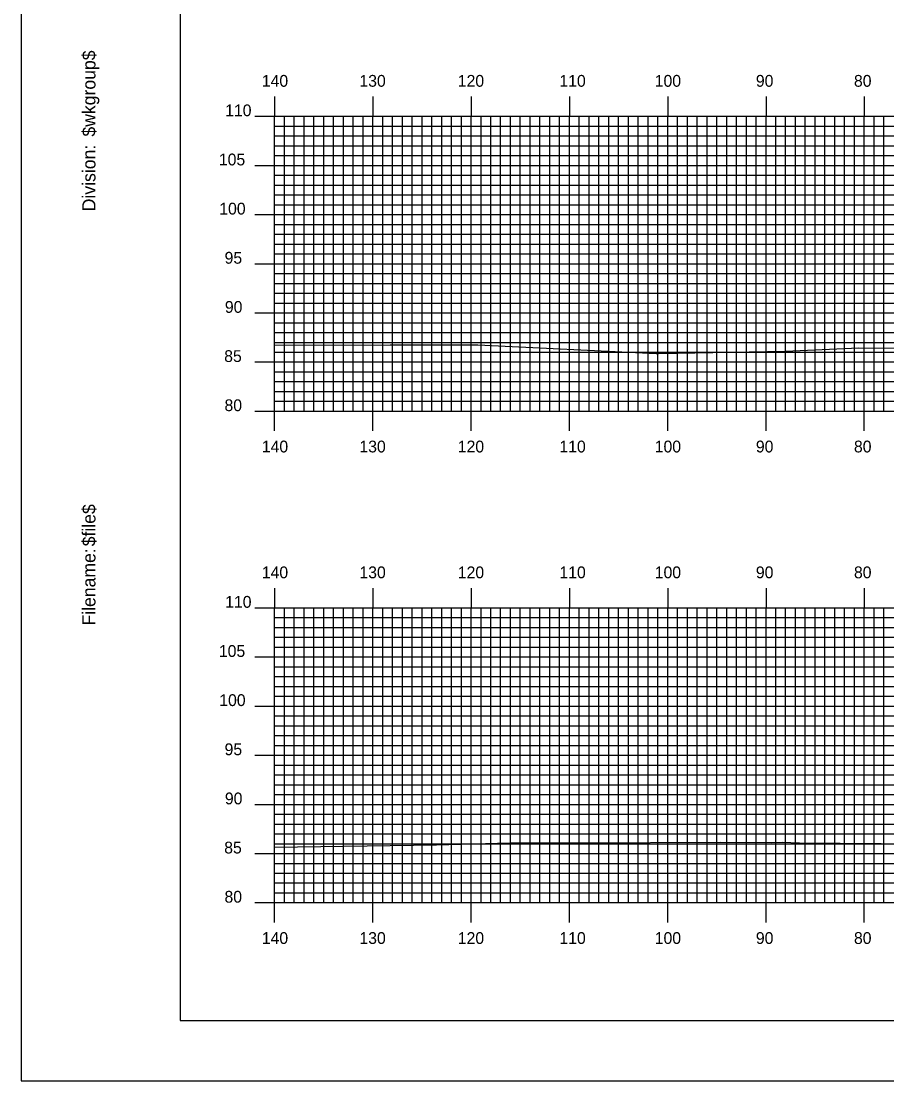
# Model space of a CAD drawing. Extents: x 1762578 to 1762921, y 442591 to 442811.
# Drawn here: x 1762578 to 1762666.1, y 442590.5 to 442698.3 of the extents above; entities that cross this region are included whole.
import ezdxf

# ---------------------------------------------------------------- set-up
doc = ezdxf.new("R2010")
doc.units = 0
for name, color, linetype in [('BORDER', 7, 'Continuous'), ('H_V ANNOTATION', 7, 'Continuous'), ('MAJOR', 7, 'Continuous'), ('MINOR', 7, 'Continuous'), ('PLOT BOUNDARY', 7, 'Continuous'), ('S_Roadway_Centerline', 7, 'Continuous')]:
    doc.layers.add(name, color=color, linetype=linetype)

msp = doc.modelspace()

# ---------------------------------------------------------------- linework, layer by layer
at = {"layer": 'BORDER'}
msp.add_lwpolyline([(1762594.18, 442596.67), (1762914.18, 442596.67), (1762914.18, 442806.67), (1762594.18, 442806.67)], close=True, dxfattribs=at)
at = {"layer": 'MAJOR'}
for p, q in [((1762603.78, 442690.67), (1762603.78, 442688.67)), ((1762613.78, 442690.67), (1762613.78, 442688.67)), ((1762623.78, 442690.67), (1762623.78, 442688.67)), ((1762633.78, 442690.67), (1762633.78, 442688.67)), ((1762643.78, 442690.67), (1762643.78, 442688.67)), ((1762653.78, 442690.67), (1762653.78, 442688.67)), ((1762663.78, 442690.67), (1762663.78, 442688.67)), ((1762601.78, 442688.67), (1762603.78, 442688.67)), ((1762603.78, 442688.67), (1762883.78, 442688.67)), ((1762603.78, 442658.67), (1762603.78, 442688.67)), ((1762603.78, 442658.67), (1762603.78, 442688.67)), ((1762603.78, 442688.67), (1762883.78, 442688.67)), ((1762613.78, 442658.67), (1762613.78, 442688.67)), ((1762623.78, 442658.67), (1762623.78, 442688.67)), ((1762633.78, 442658.67), (1762633.78, 442688.67)), ((1762643.78, 442658.67), (1762643.78, 442688.67)), ((1762653.78, 442658.67), (1762653.78, 442688.67)), ((1762663.78, 442658.67), (1762663.78, 442688.67)), ((1762601.78, 442683.67), (1762603.78, 442683.67)), ((1762603.78, 442683.67), (1762883.78, 442683.67)), ((1762601.78, 442678.67), (1762603.78, 442678.67)), ((1762603.78, 442678.67), (1762883.78, 442678.67)), ((1762601.78, 442673.67), (1762603.78, 442673.67)), ((1762603.78, 442673.67), (1762883.78, 442673.67)), ((1762601.78, 442668.67), (1762603.78, 442668.67)), ((1762603.78, 442668.67), (1762883.78, 442668.67)), ((1762601.78, 442663.67), (1762603.78, 442663.67)), ((1762603.78, 442663.67), (1762883.78, 442663.67)), ((1762601.78, 442658.67), (1762603.78, 442658.67)), ((1762603.78, 442658.67), (1762883.78, 442658.67)), ((1762603.78, 442658.67), (1762883.78, 442658.67)), ((1762603.78, 442656.66), (1762603.78, 442658.67)), ((1762613.78, 442656.66), (1762613.78, 442658.67)), ((1762623.78, 442656.66), (1762623.78, 442658.67)), ((1762633.78, 442656.66), (1762633.78, 442658.67)), ((1762643.78, 442656.66), (1762643.78, 442658.67)), ((1762653.78, 442656.66), (1762653.78, 442658.67)), ((1762663.78, 442656.66), (1762663.78, 442658.67)), ((1762603.78, 442640.67), (1762603.78, 442638.67)), ((1762613.78, 442640.67), (1762613.78, 442638.67)), ((1762623.78, 442640.67), (1762623.78, 442638.67)), ((1762633.78, 442640.67), (1762633.78, 442638.67)), ((1762643.78, 442640.67), (1762643.78, 442638.67)), ((1762653.78, 442640.67), (1762653.78, 442638.67)), ((1762663.78, 442640.67), (1762663.78, 442638.67)), ((1762601.78, 442638.67), (1762603.78, 442638.67)), ((1762603.78, 442638.67), (1762883.78, 442638.67)), ((1762603.78, 442608.67), (1762603.78, 442638.67)), ((1762603.78, 442608.67), (1762603.78, 442638.67)), ((1762603.78, 442638.67), (1762883.78, 442638.67)), ((1762613.78, 442608.67), (1762613.78, 442638.67)), ((1762623.78, 442608.67), (1762623.78, 442638.67)), ((1762633.78, 442608.67), (1762633.78, 442638.67)), ((1762643.78, 442608.67), (1762643.78, 442638.67)), ((1762653.78, 442608.67), (1762653.78, 442638.67)), ((1762663.78, 442608.67), (1762663.78, 442638.67)), ((1762601.78, 442633.67), (1762603.78, 442633.67)), ((1762603.78, 442633.67), (1762883.78, 442633.67)), ((1762601.78, 442628.67), (1762603.78, 442628.67)), ((1762603.78, 442628.67), (1762883.78, 442628.67)), ((1762601.78, 442623.67), (1762603.78, 442623.67)), ((1762603.78, 442623.67), (1762883.78, 442623.67)), ((1762601.78, 442618.67), (1762603.78, 442618.67)), ((1762603.78, 442618.67), (1762883.78, 442618.67)), ((1762601.78, 442613.67), (1762603.78, 442613.67)), ((1762603.78, 442613.67), (1762883.78, 442613.67)), ((1762601.78, 442608.67), (1762603.78, 442608.67)), ((1762603.78, 442608.67), (1762883.78, 442608.67)), ((1762603.78, 442608.67), (1762883.78, 442608.67)), ((1762603.78, 442606.66), (1762603.78, 442608.67)), ((1762613.78, 442606.66), (1762613.78, 442608.67)), ((1762623.78, 442606.66), (1762623.78, 442608.67)), ((1762633.78, 442606.66), (1762633.78, 442608.67)), ((1762643.78, 442606.66), (1762643.78, 442608.67)), ((1762653.78, 442606.66), (1762653.78, 442608.67)), ((1762663.78, 442606.66), (1762663.78, 442608.67))]:
    msp.add_line(p, q, dxfattribs=at)
at = {"layer": 'MINOR'}
for p, q in [((1762604.78, 442658.67), (1762604.78, 442688.67)), ((1762605.78, 442658.67), (1762605.78, 442688.67)), ((1762606.78, 442658.67), (1762606.78, 442688.67)), ((1762607.78, 442658.67), (1762607.78, 442688.67)), ((1762608.78, 442658.67), (1762608.78, 442688.67)), ((1762609.78, 442658.67), (1762609.78, 442688.67)), ((1762610.78, 442658.67), (1762610.78, 442688.67)), ((1762611.78, 442658.67), (1762611.78, 442688.67)), ((1762612.78, 442658.67), (1762612.78, 442688.67)), ((1762614.78, 442658.67), (1762614.78, 442688.67)), ((1762615.78, 442658.67), (1762615.78, 442688.67)), ((1762616.78, 442658.67), (1762616.78, 442688.67)), ((1762617.78, 442658.67), (1762617.78, 442688.67)), ((1762618.78, 442658.67), (1762618.78, 442688.67)), ((1762619.78, 442658.67), (1762619.78, 442688.67)), ((1762620.78, 442658.67), (1762620.78, 442688.67)), ((1762621.78, 442658.67), (1762621.78, 442688.67)), ((1762622.78, 442658.67), (1762622.78, 442688.67)), ((1762624.78, 442658.67), (1762624.78, 442688.67)), ((1762625.78, 442658.67), (1762625.78, 442688.67)), ((1762626.78, 442658.67), (1762626.78, 442688.67)), ((1762627.78, 442658.67), (1762627.78, 442688.67)), ((1762628.78, 442658.67), (1762628.78, 442688.67)), ((1762629.78, 442658.67), (1762629.78, 442688.67)), ((1762630.78, 442658.67), (1762630.78, 442688.67)), ((1762631.78, 442658.67), (1762631.78, 442688.67)), ((1762632.78, 442658.67), (1762632.78, 442688.67)), ((1762634.78, 442658.67), (1762634.78, 442688.67)), ((1762635.78, 442658.67), (1762635.78, 442688.67)), ((1762636.78, 442658.67), (1762636.78, 442688.67)), ((1762637.78, 442658.67), (1762637.78, 442688.67)), ((1762638.78, 442658.67), (1762638.78, 442688.67)), ((1762639.78, 442658.67), (1762639.78, 442688.67)), ((1762640.78, 442658.67), (1762640.78, 442688.67)), ((1762641.78, 442658.67), (1762641.78, 442688.67)), ((1762642.78, 442658.67), (1762642.78, 442688.67)), ((1762644.78, 442658.67), (1762644.78, 442688.67)), ((1762645.78, 442658.67), (1762645.78, 442688.67)), ((1762646.78, 442658.67), (1762646.78, 442688.67)), ((1762647.78, 442658.67), (1762647.78, 442688.67)), ((1762648.78, 442658.67), (1762648.78, 442688.67)), ((1762649.78, 442658.67), (1762649.78, 442688.67)), ((1762650.78, 442658.67), (1762650.78, 442688.67)), ((1762651.78, 442658.67), (1762651.78, 442688.67)), ((1762652.78, 442658.67), (1762652.78, 442688.67)), ((1762654.78, 442658.67), (1762654.78, 442688.67)), ((1762655.78, 442658.67), (1762655.78, 442688.67)), ((1762656.78, 442658.67), (1762656.78, 442688.67)), ((1762657.78, 442658.67), (1762657.78, 442688.67)), ((1762658.78, 442658.67), (1762658.78, 442688.67)), ((1762659.78, 442658.67), (1762659.78, 442688.67)), ((1762660.78, 442658.67), (1762660.78, 442688.67)), ((1762661.78, 442658.67), (1762661.78, 442688.67)), ((1762662.78, 442658.67), (1762662.78, 442688.67)), ((1762664.78, 442658.67), (1762664.78, 442688.67)), ((1762665.78, 442658.67), (1762665.78, 442688.67)), ((1762603.78, 442687.67), (1762883.78, 442687.67)), ((1762603.78, 442687.67), (1762605.78, 442687.67)), ((1762603.78, 442686.67), (1762883.78, 442686.67)), ((1762603.78, 442686.67), (1762605.78, 442686.67)), ((1762603.78, 442685.67), (1762883.78, 442685.67)), ((1762603.78, 442685.67), (1762605.78, 442685.67)), ((1762603.78, 442684.67), (1762883.78, 442684.67)), ((1762603.78, 442684.67), (1762605.78, 442684.67)), ((1762603.78, 442682.67), (1762883.78, 442682.67)), ((1762603.78, 442682.67), (1762605.78, 442682.67)), ((1762603.78, 442681.67), (1762883.78, 442681.67)), ((1762603.78, 442681.67), (1762605.78, 442681.67)), ((1762603.78, 442680.67), (1762883.78, 442680.67)), ((1762603.78, 442680.67), (1762605.78, 442680.67)), ((1762603.78, 442679.67), (1762883.78, 442679.67)), ((1762603.78, 442679.67), (1762605.78, 442679.67)), ((1762603.78, 442677.67), (1762883.78, 442677.67)), ((1762603.78, 442677.67), (1762605.78, 442677.67)), ((1762603.78, 442676.67), (1762883.78, 442676.67)), ((1762603.78, 442676.67), (1762605.78, 442676.67)), ((1762603.78, 442675.67), (1762883.78, 442675.67)), ((1762603.78, 442675.67), (1762605.78, 442675.67)), ((1762603.78, 442674.67), (1762883.78, 442674.67)), ((1762603.78, 442674.67), (1762605.78, 442674.67)), ((1762603.78, 442672.67), (1762883.78, 442672.67)), ((1762603.78, 442672.67), (1762605.78, 442672.67)), ((1762603.78, 442671.67), (1762883.78, 442671.67)), ((1762603.78, 442671.67), (1762605.78, 442671.67)), ((1762603.78, 442670.67), (1762883.78, 442670.67)), ((1762603.78, 442670.67), (1762605.78, 442670.67)), ((1762603.78, 442669.67), (1762883.78, 442669.67)), ((1762603.78, 442669.67), (1762605.78, 442669.67)), ((1762603.78, 442667.67), (1762883.78, 442667.67)), ((1762603.78, 442667.67), (1762605.78, 442667.67)), ((1762603.78, 442666.67), (1762883.78, 442666.67)), ((1762603.78, 442666.67), (1762605.78, 442666.67)), ((1762603.78, 442665.67), (1762883.78, 442665.67)), ((1762603.78, 442665.67), (1762605.78, 442665.67)), ((1762603.78, 442664.67), (1762883.78, 442664.67)), ((1762603.78, 442664.67), (1762605.78, 442664.67)), ((1762603.78, 442662.67), (1762883.78, 442662.67)), ((1762603.78, 442662.67), (1762605.78, 442662.67)), ((1762603.78, 442661.67), (1762883.78, 442661.67)), ((1762603.78, 442661.67), (1762605.78, 442661.67)), ((1762603.78, 442660.67), (1762883.78, 442660.67)), ((1762603.78, 442660.67), (1762605.78, 442660.67)), ((1762603.78, 442659.67), (1762883.78, 442659.67)), ((1762603.78, 442659.67), (1762605.78, 442659.67)), ((1762604.78, 442608.67), (1762604.78, 442638.67)), ((1762605.78, 442608.67), (1762605.78, 442638.67)), ((1762606.78, 442608.67), (1762606.78, 442638.67)), ((1762607.78, 442608.67), (1762607.78, 442638.67)), ((1762608.78, 442608.67), (1762608.78, 442638.67)), ((1762609.78, 442608.67), (1762609.78, 442638.67)), ((1762610.78, 442608.67), (1762610.78, 442638.67)), ((1762611.78, 442608.67), (1762611.78, 442638.67)), ((1762612.78, 442608.67), (1762612.78, 442638.67)), ((1762614.78, 442608.67), (1762614.78, 442638.67)), ((1762615.78, 442608.67), (1762615.78, 442638.67)), ((1762616.78, 442608.67), (1762616.78, 442638.67)), ((1762617.78, 442608.67), (1762617.78, 442638.67)), ((1762618.78, 442608.67), (1762618.78, 442638.67)), ((1762619.78, 442608.67), (1762619.78, 442638.67)), ((1762620.78, 442608.67), (1762620.78, 442638.67)), ((1762621.78, 442608.67), (1762621.78, 442638.67)), ((1762622.78, 442608.67), (1762622.78, 442638.67)), ((1762624.78, 442608.67), (1762624.78, 442638.67)), ((1762625.78, 442608.67), (1762625.78, 442638.67)), ((1762626.78, 442608.67), (1762626.78, 442638.67)), ((1762627.78, 442608.67), (1762627.78, 442638.67)), ((1762628.78, 442608.67), (1762628.78, 442638.67)), ((1762629.78, 442608.67), (1762629.78, 442638.67)), ((1762630.78, 442608.67), (1762630.78, 442638.67)), ((1762631.78, 442608.67), (1762631.78, 442638.67)), ((1762632.78, 442608.67), (1762632.78, 442638.67)), ((1762634.78, 442608.67), (1762634.78, 442638.67)), ((1762635.78, 442608.67), (1762635.78, 442638.67)), ((1762636.78, 442608.67), (1762636.78, 442638.67)), ((1762637.78, 442608.67), (1762637.78, 442638.67)), ((1762638.78, 442608.67), (1762638.78, 442638.67)), ((1762639.78, 442608.67), (1762639.78, 442638.67)), ((1762640.78, 442608.67), (1762640.78, 442638.67)), ((1762641.78, 442608.67), (1762641.78, 442638.67)), ((1762642.78, 442608.67), (1762642.78, 442638.67)), ((1762644.78, 442608.67), (1762644.78, 442638.67)), ((1762645.78, 442608.67), (1762645.78, 442638.67)), ((1762646.78, 442608.67), (1762646.78, 442638.67)), ((1762647.78, 442608.67), (1762647.78, 442638.67)), ((1762648.78, 442608.67), (1762648.78, 442638.67)), ((1762649.78, 442608.67), (1762649.78, 442638.67)), ((1762650.78, 442608.67), (1762650.78, 442638.67)), ((1762651.78, 442608.67), (1762651.78, 442638.67)), ((1762652.78, 442608.67), (1762652.78, 442638.67)), ((1762654.78, 442608.67), (1762654.78, 442638.67)), ((1762655.78, 442608.67), (1762655.78, 442638.67)), ((1762656.78, 442608.67), (1762656.78, 442638.67)), ((1762657.78, 442608.67), (1762657.78, 442638.67)), ((1762658.78, 442608.67), (1762658.78, 442638.67)), ((1762659.78, 442608.67), (1762659.78, 442638.67)), ((1762660.78, 442608.67), (1762660.78, 442638.67)), ((1762661.78, 442608.67), (1762661.78, 442638.67)), ((1762662.78, 442608.67), (1762662.78, 442638.67)), ((1762664.78, 442608.67), (1762664.78, 442638.67)), ((1762665.78, 442608.67), (1762665.78, 442638.67)), ((1762603.78, 442637.67), (1762883.78, 442637.67)), ((1762603.78, 442637.67), (1762605.78, 442637.67)), ((1762603.78, 442636.67), (1762883.78, 442636.67)), ((1762603.78, 442636.67), (1762605.78, 442636.67)), ((1762603.78, 442635.67), (1762883.78, 442635.67)), ((1762603.78, 442635.67), (1762605.78, 442635.67)), ((1762603.78, 442634.67), (1762883.78, 442634.67)), ((1762603.78, 442634.67), (1762605.78, 442634.67)), ((1762603.78, 442632.67), (1762883.78, 442632.67)), ((1762603.78, 442632.67), (1762605.78, 442632.67)), ((1762603.78, 442631.67), (1762883.78, 442631.67)), ((1762603.78, 442631.67), (1762605.78, 442631.67)), ((1762603.78, 442630.67), (1762883.78, 442630.67)), ((1762603.78, 442630.67), (1762605.78, 442630.67)), ((1762603.78, 442629.67), (1762883.78, 442629.67)), ((1762603.78, 442629.67), (1762605.78, 442629.67)), ((1762603.78, 442627.67), (1762883.78, 442627.67)), ((1762603.78, 442627.67), (1762605.78, 442627.67)), ((1762603.78, 442626.67), (1762883.78, 442626.67)), ((1762603.78, 442626.67), (1762605.78, 442626.67)), ((1762603.78, 442625.67), (1762883.78, 442625.67)), ((1762603.78, 442625.67), (1762605.78, 442625.67)), ((1762603.78, 442624.67), (1762883.78, 442624.67)), ((1762603.78, 442624.67), (1762605.78, 442624.67)), ((1762603.78, 442622.67), (1762883.78, 442622.67)), ((1762603.78, 442622.67), (1762605.78, 442622.67)), ((1762603.78, 442621.67), (1762883.78, 442621.67)), ((1762603.78, 442621.67), (1762605.78, 442621.67)), ((1762603.78, 442620.67), (1762883.78, 442620.67)), ((1762603.78, 442620.67), (1762605.78, 442620.67)), ((1762603.78, 442619.67), (1762883.78, 442619.67)), ((1762603.78, 442619.67), (1762605.78, 442619.67)), ((1762603.78, 442617.67), (1762883.78, 442617.67)), ((1762603.78, 442617.67), (1762605.78, 442617.67)), ((1762603.78, 442616.67), (1762883.78, 442616.67)), ((1762603.78, 442616.67), (1762605.78, 442616.67)), ((1762603.78, 442615.67), (1762883.78, 442615.67)), ((1762603.78, 442615.67), (1762605.78, 442615.67)), ((1762603.78, 442614.67), (1762883.78, 442614.67)), ((1762603.78, 442614.67), (1762605.78, 442614.67)), ((1762603.78, 442612.67), (1762883.78, 442612.67)), ((1762603.78, 442612.67), (1762605.78, 442612.67)), ((1762603.78, 442611.67), (1762883.78, 442611.67)), ((1762603.78, 442611.67), (1762605.78, 442611.67)), ((1762603.78, 442610.67), (1762883.78, 442610.67)), ((1762603.78, 442610.67), (1762605.78, 442610.67)), ((1762603.78, 442609.67), (1762883.78, 442609.67)), ((1762603.78, 442609.67), (1762605.78, 442609.67))]:
    msp.add_line(p, q, dxfattribs=at)
at = {"layer": 'PLOT BOUNDARY'}
msp.add_lwpolyline([(1762577.99, 442590.55), (1762917.99, 442590.55), (1762917.99, 442810.55), (1762577.99, 442810.55)], close=True, dxfattribs=at)
at = {"layer": 'S_Roadway_Centerline'}
for points in [[(1762603.78, 442665.37), (1762615.54, 442665.43), (1762624.45, 442665.41), (1762642.62, 442664.55), (1762642.69, 442664.55), (1762642.85, 442664.55), (1762655.78, 442664.78), (1762663.21, 442665.11), (1762674.57, 442665.04)], [(1762603.78, 442614.31), (1762620.26, 442614.55), (1762627.71, 442614.76), (1762634.89, 442614.75), (1762649.1, 442614.83), (1762654.39, 442614.78), (1762655.42, 442614.81), (1762657.2, 442614.76), (1762673.81, 442614.61)]]:
    msp.add_lwpolyline(points, dxfattribs=at)

# ---------------------------------------------------------------- texts
at = {"layer": 'BORDER'}
for s, p in [('$wkgroup$', (1762585.55, 442686.6)), ('Division:', (1762585.55, 442679)), ('$file$', (1762585.55, 442644.92)), ('Filename:', (1762585.55, 442636.86))]:
    msp.add_text(s, height=1.339, rotation=90, dxfattribs=at).set_placement(p)
at = {"layer": 'H_V ANNOTATION'}
for s, p in [('140', (1762602.48, 442691.67)), ('130', (1762612.41, 442691.67)), ('120', (1762622.42, 442691.67)), ('110', (1762632.76, 442691.67)), ('100', (1762642.46, 442691.67)), ('90', (1762652.75, 442691.67)), ('80', (1762662.73, 442691.67)), ('110', (1762598.75, 442688.67)), ('105', (1762598.11, 442683.67)), ('100', (1762598.15, 442678.67)), ('95', (1762598.69, 442673.67)), ('90', (1762598.72, 442668.67)), ('85', (1762598.65, 442663.67)), ('80', (1762598.68, 442658.67)), ('140', (1762602.48, 442654.47)), ('130', (1762612.41, 442654.47)), ('120', (1762622.42, 442654.47)), ('110', (1762632.76, 442654.47)), ('100', (1762642.46, 442654.47)), ('90', (1762652.75, 442654.47)), ('80', (1762662.73, 442654.47)), ('140', (1762602.48, 442641.67)), ('130', (1762612.41, 442641.67)), ('120', (1762622.42, 442641.67)), ('110', (1762632.76, 442641.67)), ('100', (1762642.46, 442641.67)), ('90', (1762652.75, 442641.67)), ('80', (1762662.73, 442641.67)), ('110', (1762598.75, 442638.67)), ('105', (1762598.11, 442633.67)), ('100', (1762598.15, 442628.67)), ('95', (1762598.69, 442623.67)), ('90', (1762598.72, 442618.67)), ('85', (1762598.65, 442613.67)), ('80', (1762598.68, 442608.67)), ('140', (1762602.48, 442604.47)), ('130', (1762612.41, 442604.47)), ('120', (1762622.42, 442604.47)), ('110', (1762632.76, 442604.47)), ('100', (1762642.46, 442604.47)), ('90', (1762652.75, 442604.47)), ('80', (1762662.73, 442604.47))]:
    msp.add_text(s, height=1.2, dxfattribs=at).set_placement(p)
at = {"layer": 'MAJOR'}
for p in [(1762603.77, 442658.67), (1762603.77, 442608.67)]:
    msp.add_text('-', height=0.012, dxfattribs=at).set_placement(p)

doc.saveas('drawing.dxf')
